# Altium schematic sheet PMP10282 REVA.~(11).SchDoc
size 431 x 279 mm; Date: Not shown in title block; ApprovedBy: Not shown in title block; CheckedBy: Not shown in title block; Author: Not shown in title block; CompanyName: Not shown in title block; Engineer: Not shown in title block; Organization: Not shown in title block; Address1: Not shown in title block; Address2: Not shown in title block; Address3: Not shown in title block; Address4: Not shown in title block; DocumentNumber: 1; Revision: Use project parameter SCH_Rev; SheetNumber: 1; SheetTotal: 1; PageSetup: Record=PageOptions|CenterHorizontal=True|CenterVertical=True|PrintScale=1.00|XCorrection=1.00|YCorrection=1.00|PrintKind=0|BorderSize=5000000|LeftOffset=0|BottomOffset=0|Orientation=2|PaperLength=1000|PaperWidth=1000|Scale=100|PaperSource=15|PrintQuality=600|MediaType=1|DitherType=10|PaperKind=Letter|PrintScaleMode=1
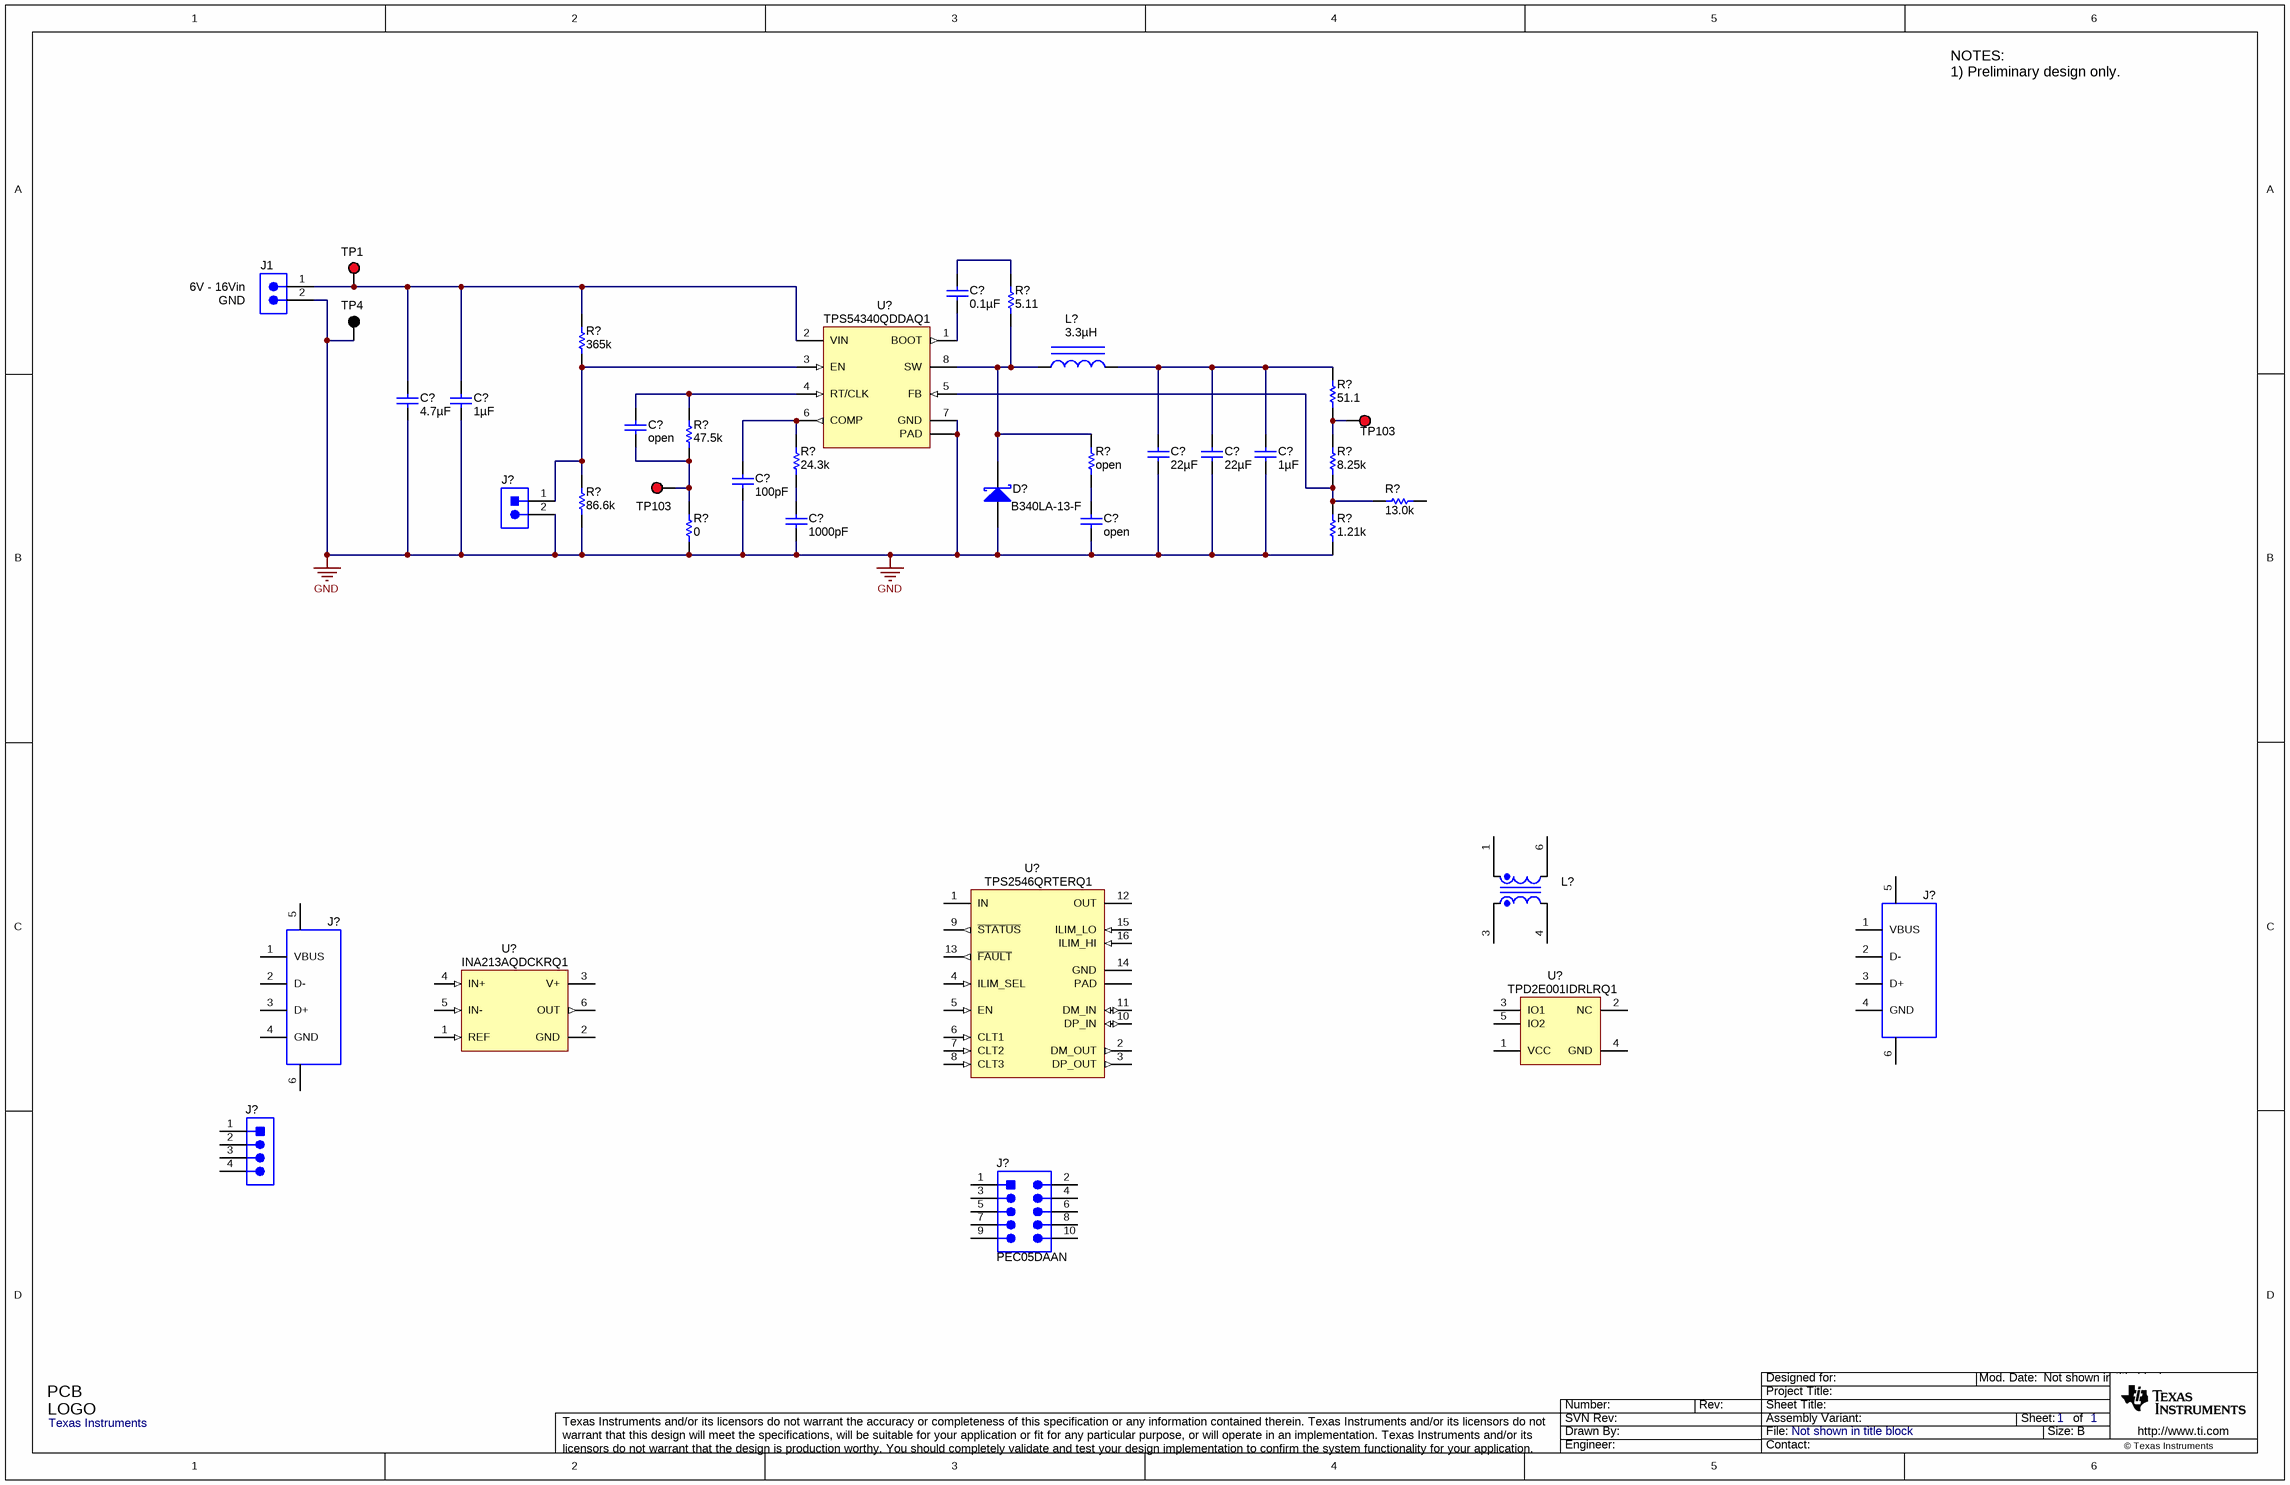
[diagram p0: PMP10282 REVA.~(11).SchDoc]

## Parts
(Parts that share a designator on the sheet are numbered #1, #2 ... from top to bottom, then left to right.)
C?#1  ValueDisplayed: 0.1µF  [0402]  (hidden comment: C1005X7R1H104K050BB)
C?#2  ValueDisplayed: 4.7µF  [1206]  (hidden comment: GRM31CR71H475KA12L)
C?#3  ValueDisplayed: 1µF  [0603]  (hidden comment: UMK107AB7105KA-T)
C?#4  ValueDisplayed: open  [0402]
C?#5  ValueDisplayed: 22µF  [0805_HV]  (hidden comment: GRM21BR61A226ME44)
C?#6  ValueDisplayed: 22µF  [0805_HV]  (hidden comment: GRM21BR61A226ME44)
C?#7  ValueDisplayed: 1µF  [0603]  (hidden comment: UMK107AB7105KA-T)
C?#8  ValueDisplayed: 100pF  [0402]  (hidden comment: GRM1535C1H101JDD5D)
C?#9  ValueDisplayed: 1000pF  [0402]  (hidden comment: C1005C0G1E102J)
C?#10  ValueDisplayed: open  [0402]
D?  B340LA-13-F  [SMA]
J1  ED555/2DS  [TERM_BLK_ED555-2DS]  (value not drawn)
J?#1  PEC02SAAN  [CONN_PEC02SAAN]  (value not drawn)
J?#2  896-43-004-00-000000  [CONN_USB_896-43-004-00-000000]  (value not drawn)
J?#3  896-43-004-00-000000  [CONN_USB_896-43-004-00-000000]  (value not drawn)
J?#4  PEC04SAAN  [SULLINS_PEC04SAAN]  (value not drawn)
J?#5  PEC05DAAN  [CONN_PEC05DAAN]
L?#1  ValueDisplayed: 3.3µH  [SPM6530]  (hidden comment: SPM6530T-3R3M)
L?#2  985DH-1026  [NT2012]  (value not drawn)
Logo1  Texas Instruments  [TI_Stacked_Overlay_Small]  (no BOM)
R?#1  value 5.11  [0603]  (hidden comment: CRCW06035R11FKEA)
R?#2  value 365k  [0402]  (hidden comment: CRCW0402365KFKED)
R?#3  value 51.1  [0402]  (hidden comment: CRCW040251R1FKED)
R?#4  value 47.5k  [0402]  (hidden comment: CRCW040247K5FKED)
R?#5  value 24.3k  [0402]  (hidden comment: CRCW040224K3FKED)
R?#6  value open  [0805_HV]
R?#7  value 8.25k  [0402]  (hidden comment: CRCW04028K25FKED)
R?#8  value 86.6k  [0402]  (hidden comment: CRCW040286K6FKED)
R?#9  value 13.0k  [0402]  (hidden comment: CRCW040213K0FKED)
R?#10  value 0  [0402]  (hidden comment: CRCW04020000Z0ED)
R?#11  value 1.21k  [0402]  (hidden comment: CRCW04021K21FKED)
TP1  5000  [Keystone5000]  (value not drawn)
TP4  5001  [Keystone5001]  (value not drawn)
TP103#1  5010  [Keystone5010]  (value not drawn)
TP103#2  5010  [Keystone5010]  (value not drawn)
U?#1  TPS54340QDDAQ1  [DDA0008E_N]
U?#2  TPS2546QRTERQ1  [RTE0016C]
U?#3  TPD2E001IDRLRQ1  [DRL0005A]
U?#4  INA213AQDCKRQ1  [DCK0006A_N]

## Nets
GND: C?#2.2 C?#3.2 C?#5.2 C?#6.2 C?#7.2 C?#8.2 C?#9.2 C?#10.2 D?.2(A) J1.2 J?#1.2 R?#8.1 R?#10.1 R?#11.1 TP4.1 U?#1.7(GND) U?#1.9(PAD)
NetC?#1_1: C?#1.1 R?#1.2
NetC?#1_2: C?#1.2 U?#1.1(BOOT)
NetC?#2_1: C?#2.1 C?#3.1 J1.1 R?#2.2 TP1.1 U?#1.2(VIN)
NetC?#4_1: C?#4.1 R?#4.2 U?#1.4(RT/CLK)
NetC?#4_2: C?#4.2 R?#4.1 R?#10.2 TP103#2.1
NetC?#5_1: C?#5.1 C?#6.1 C?#7.1 L?#1.2 R?#3.2
NetC?#8_1: C?#8.1 R?#5.2 U?#1.6(COMP)
NetC?#9_1: C?#9.1 R?#5.1
NetC?#10_1: C?#10.1 R?#6.1
NetD?_1: D?.1(K) L?#1.1 R?#1.1 R?#6.2 U?#1.8(SW)
NetJ?#1_1: J?#1.1 R?#2.1 R?#8.2 U?#1.3(EN)
NetR?#3_1: R?#3.1 R?#7.2 TP103#1.1
NetR?#7_1: R?#7.1 R?#9.2 R?#11.2 U?#1.5(FB)

Not connected (* = marked no-connect by the designer): J?#2 1(VBUS) 2(D-) 3(D+) 4(GND) 5(Shield) 6(Shield); J?#3 1(VBUS) 2(D-) 3(D+) 4(GND) 5(Shield) 6(Shield); J?#4 1 2 3 4; J?#5 1 2 3 4 5 6 7 8 9 10; L?#2 1 3 4 6; R?#9 1; U?#2 1(IN) 2(DM_OUT) 3(DP_OUT) 4(ILIM_SEL) 5(EN) 6(CLT1) 7(CLT2) 8(CLT3) 9(~{STATUS}) 10(DP_IN) 11(DM_IN) 12(OUT) 13(~{FAULT}) 14(GND) 15(ILIM_LO) 16(ILIM_HI) 17(PAD); U?#3 1(VCC) 2(NC) 3(IO1) 4(GND) 5(IO2); U?#4 1(REF) 2(GND) 3(V+) 4(IN+) 5(IN-) 6(OUT)

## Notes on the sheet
- NOTES:
  1) Preliminary design only.
- (near J1) 6V - 16Vin
- (near J1) GND

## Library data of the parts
C?#1 = C1005X7R1H104K050BB: CAP, CERM, 0.1uF, 50V, +/-10%, X7R, 0402; Manufacturer: TDK; Polarized: N; CompType: Capacitor; U/M: EA; Cap_F: 0.0000001; Tolerance_%: 10; Value1: Unknown; VDC_V: 50; TaMin_C: -55; TaMax_C: 125
C?#2 = GRM31CR71H475KA12L: CAP, CERM, 4.7uF, 50V, +/-10%, X7R, 1206; Manufacturer: MuRata; Polarized: N; CompType: Capacitor; U/M: EA; Cap_F: 0.0000047; Tolerance_%: 10; Value1: Unknown; VDC_V: 50; TaMin_C: -55; TaMax_C: 125; Cap_Case: 2220
C?#3 C?#7 = UMK107AB7105KA-T: CAP, CERM, 1uF, 50V, +/-10%, X7R, 0603; Manufacturer: Taiyo Yuden; Polarized: N; CompType: Capacitor; U/M: EA; Cap_F: 0.000001; Tolerance_%: 10; Value1: Unknown; VDC_V: 50; TaMin_C: -55; TaMax_C: 125
C?#4 = C1005X7R1H104K050BB: CAP, open, 0402; Polarized: N; CompType: Capacitor; U/M: EA; Cap_F: 0.0000001; Tolerance_%: 10; Value1: Unknown; TaMin_C: -55; TaMax_C: 125
C?#5 C?#6 = GRM21BR61A226ME44: CAP, CERM, 22uF, 10V, +/-20%, X5R, 0805; Manufacturer: MuRata; Polarized: N; CompType: Capacitor; U/M: EA; Cap_F: 0.000022; Tolerance_%: 20; Value1: Unknown; VDC_V: 10; TaMin_C: -55; TaMax_C: 85; Cap_Case: 0805
C?#8 = GRM1535C1H101JDD5D: CAP, CERM, 100pF, 50V, +/-5%, C0G/NP0, 0402; Manufacturer: MuRata; Polarized: N; CompType: Capacitor; U/M: EA; Cap_F: 0.0000000001; Tolerance_%: 5; Value1: Unknown; VDC_V: 50; TaMin_C: -55; TaMax_C: 125
C?#9 = C1005C0G1E102J: CAP, CERM, 1000pF, 25V, +/-5%, C0G/NP0, 0402; Manufacturer: TDK; Polarized: N; CompType: Capacitor; U/M: EA; Cap_F: 0.000000001; Tolerance_%: 5; Value1: Unknown; VDC_V: 25; TaMin_C: -55; TaMax_C: 125
C?#10 = C1005C0G1E102J: CAP, open, 0402; Polarized: N; CompType: Capacitor; U/M: EA; Cap_F: 0.000000001; Tolerance_%: 5; Value1: Unknown; TempCo: C0G/NP0; TaMin_C: -55; TaMax_C: 125
D? = B340LA-13-F: Diode, Schottky, 40V, 3A, SMA; Manufacturer: Diodes Inc.; U/M: EA; Vf_V: 0.45; Value2: 0.45V; Io_A: 3; Vr_V: 40; TJmax_C: 125; RJC_CperW: 25
J1 = ED555/2DS: Terminal Block, 6A, 3.5mm Pitch, 2-Pos, TH; Manufacturer: On-Shore Technology, Inc.; SymbolCreator: a0412235; CompType: Connector; U/M: EA
J?#1 = PEC02SAAN: Header, 100mil, 2x1, Tin, TH; Manufacturer: Sullins Connector Solutions; SymbolCreator: a0412235; U/M: EA
J?#2 J?#3 = 896-43-004-00-000000: Connector, Receptacle, USB TYPE A, R/A, Top Mount SMT; Manufacturer: Mill-Max; SymbolCreator: a0412235; U/M: EA
J?#4 = PEC04SAAN: Header, 100mil, 4x1, Tin, TH; Manufacturer: Sullins Connector Solutions; SymbolCreator: a0412235; U/M: EA
J?#5 = PEC05DAAN: Header, 100mil, 5x2, Tin plated, TH; Manufacturer: Sullins Connector Solutions; SymbolCreator: a0412235; U/M: EA
L?#1 = SPM6530T-3R3M: Inductor, Shielded, Ferrite, 3.3uH, 6.8A, 0.0297 ohm, SMD; Manufacturer: TDK; Ind_H: 3.3E-6; Imax_A: 6.8; Irms: 6.8A @ 40C rise; Isat: 7.3A @ 20% inductance drop; DCR_ohm: 0.0297
L?#2 = 985DH-1023: Coupled inductor, 0.28A, 0.36 ohm, SMD; Manufacturer: Toko; SymbolCreator: a0411947; DCR_ohm: 0.21; Isat: 0.37
Logo1 = TI_Logo: Texas Instrument Corporate Signature; SymbolCreator: a0412235
R?#1 = CRCW06035R11FKEA: RES, 5.11 ohm, 1%, 0.1W, 0603; Manufacturer: Vishay-Dale; CompType: Resistor; Value_Code: 5R11; Tolerance_%: 1; Power_W: 0.1; VDC_V: 75; TempCo: 100 ppm/C; EIA_Code: E96; U/M: EA
R?#2 = CRCW0402365KFKED: RES, 365k ohm, 1%, 0.063W, 0402; Manufacturer: Vishay-Dale; CompType: Resistor; Res_ohm: 365000; Tolerance_%: 1; Power_W: 0.063; VDC_V: 50; TempCo: 100 ppm/C; EIA_Code: E96; U/M: EA
R?#3 = CRCW040251R1FKED: RES, 51.1 ohm, 1%, 0.063W, 0402; Manufacturer: Vishay-Dale; CompType: Resistor; Value_Code: 51R1; Tolerance_%: 1; Power_W: 0.063; VDC_V: 50; TempCo: 100 ppm/C; EIA_Code: E96; U/M: EA
R?#4 = CRCW040247K5FKED: RES, 47.5k ohm, 1%, 0.063W, 0402; Manufacturer: Vishay-Dale; CompType: Resistor; Res_ohm: 47500; Value_Code: 47k5; Tolerance_%: 1; Power_W: 0.063; VDC_V: 50; TempCo: 100 ppm/C; EIA_Code: E96; U/M: EA
R?#5 = CRCW040224K3FKED: RES, 24.3k ohm, 1%, 0.063W, 0402; Manufacturer: Vishay-Dale; CompType: Resistor; Res_ohm: 24300; Value_Code: 24k3; Tolerance_%: 1; Power_W: 0.063; VDC_V: 50; TempCo: 100 ppm/C; EIA_Code: E96; U/M: EA
R?#6 = CRCW08051K78FKEA: RES, open, 0805; CompType: Resistor; Res_ohm: 1780; Tolerance_%: 1; Power_W: 0.125; TempCo: 100 ppm/C; EIA_Code: E96; U/M: EA
R?#7 = CRCW04028K25FKED: RES, 8.25k ohm, 1%, 0.063W, 0402; Manufacturer: Vishay-Dale; CompType: Resistor; Res_ohm: 8250; Value_Code: 8k25; Tolerance_%: 1; Power_W: 0.063; VDC_V: 50; TempCo: 100 ppm/C; EIA_Code: E96; U/M: EA
R?#8 = CRCW040286K6FKED: RES, 86.6k ohm, 1%, 0.063W, 0402; Manufacturer: Vishay-Dale; CompType: Resistor; Res_ohm: 86600; Value_Code: 86k6; Tolerance_%: 1; Power_W: 0.063; VDC_V: 50; TempCo: 100 ppm/C; EIA_Code: E96; U/M: EA
R?#9 = CRCW040213K0FKED: RES, 13.0k ohm, 1%, 0.063W, 0402; Manufacturer: Vishay-Dale; CompType: Resistor; Res_ohm: 13000; Value_Code: 13k0; Tolerance_%: 1; Power_W: 0.063; VDC_V: 50; TempCo: 100 ppm/C; EIA_Code: E96; U/M: EA
R?#10 = CRCW04020000Z0ED: RES, 0 ohm, 5%, 0.063W, 0402; Manufacturer: Vishay-Dale; CompType: Resistor; Value_Code: 0000; Tolerance_%: 5; Power_W: 0.063; VDC_V: 50; TempCo: 200 ppm/C; EIA_Code: E24; U/M: EA
R?#11 = CRCW04021K21FKED: RES, 1.21k ohm, 1%, 0.063W, 0402; Manufacturer: Vishay-Dale; CompType: Resistor; Res_ohm: 1210; Value_Code: 1k21; Tolerance_%: 1; Power_W: 0.063; VDC_V: 50; TempCo: 100 ppm/C; EIA_Code: E96; U/M: EA
TP1 = 5000: Test Point, TH, Miniature, Red; Manufacturer: Keystone; CompType: Test Point Loop; U/M: EA
TP4 = 5001: Test Point, TH, Miniature, Black; Manufacturer: Keystone; CompType: Test Point Loop; U/M: EA
TP103#1 TP103#2 = 5010: Test Point, Multipurpose, Red, TH; Manufacturer: Keystone; CompType: Test Point Loop; U/M: EA
U?#1 = TPS54340DDA: 42 V Input, 3.5 A, Step Down DC-DC Converter with Eco-mode, DDA0008E; Alternate Manufacturer: None; Manufacturer: Texas Instruments; SymbolCreator: a0411947; CompType: IC; U/M: EA
U?#2 = TPS2546RTE: USB Charging Port Controller and Power Switch with Load Detection, RTE0016C; Alternate Manufacturer: None; Manufacturer: Texas Instruments; SymbolCreator: a0411947; CompType: IC; U/M: EA
U?#3 = TPD2E001IDRLRQ1: Automotive Catalog Low-Capacitance + / - 15 kV ESD-Protection Array for High-Speed Data Inter, 2 Channels, -40 to +85 degC, 5-pin SOT (DRL), Green (RoHS & no Sb/Br); Manufacturer: Texas Instruments; Alternate Manufacturer: None; Alternate PartNumber: Equivalent; Breakdown Voltage(Min)(V): 11; IEC 61000-4-2 Air-Gap(+/- kV): 15; IEC 61000-4-2 Contact(+/- kV): 8; IO Capacitance(Typ)(pF): 1.5; IO Leakage Current(nA): 1; SubFamily: ESD Solution; USB High Speed: TRUE
U?#4 = INA213AIDCK: Voltage Output, High or Low Side Measurement, Bi-Directional Zero-Drift Series Current-Shunt Monitor, DCK0006A; Alternate Manufacturer: None; Manufacturer: Texas Instruments; SymbolCreator: a0411947; CompType: IC; U/M: EA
